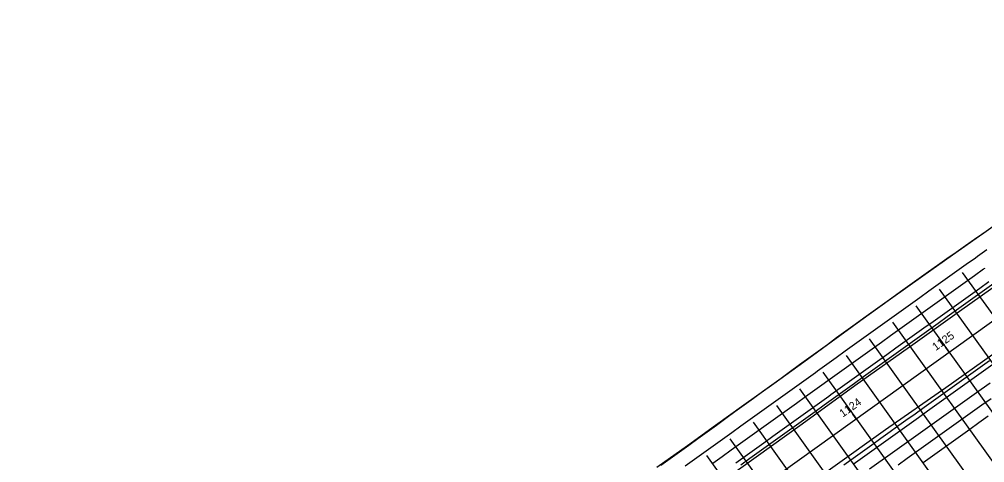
# Model space of a CAD drawing. Extents: x -354 to 8821, y -19535 to 19639.
# Drawn here: x 7398 to 8242, y 2193 to 2581 of the extents above; entities that cross this region are included whole.
import ezdxf

# ---------------------------------------------------------------- set-up
doc = ezdxf.new("R2010")
doc.units = 0
for name, color, linetype in [('PV_X_COP', 7, 'Continuous'), ('PV_X_EOP', 7, 'Continuous'), ('PV_X_Shoulder_Aggregate', 7, 'Continuous'), ('RW_X_CL_50', 7, 'Continuous'), ('SC_Scratch1', 7, 'Continuous')]:
    doc.layers.add(name, color=color, linetype=linetype)

msp = doc.modelspace()

# ---------------------------------------------------------------- linework, layer by layer
at = {"layer": 'PV_X_COP'}
for points in [[(8167.57, 2310.25), (8175.7, 2316.07), (8183.83, 2321.89), (8191.96, 2327.72), (8200.09, 2333.54), (8208.22, 2339.36), (8216.35, 2345.18), (8224.49, 2351), (8232.62, 2356.82), (8240.75, 2362.63), (8241.93, 2363.47)], [(8003.89, 2192.82), (8012.01, 2198.66), (8020.13, 2204.49), (8028.25, 2210.33), (8036.38, 2216.16), (8044.5, 2221.99), (8052.62, 2227.82), (8060.75, 2233.65), (8068.87, 2239.48), (8077, 2245.31), (8085.12, 2251.14), (8093.25, 2256.97), (8101.37, 2262.8), (8102.55, 2263.64), (8110.67, 2269.47), (8118.8, 2275.3), (8126.93, 2281.12), (8135.06, 2286.95), (8143.18, 2292.78), (8151.31, 2298.6), (8159.44, 2304.42), (8167.57, 2310.25)], [(8140.96, 2187.7), (8149.1, 2193.51), (8157.06, 2199.2), (8165.19, 2205.02), (8173.33, 2210.83), (8181.47, 2216.64), (8189.61, 2222.45), (8197.74, 2228.26), (8205.88, 2234.08), (8214.02, 2239.89), (8222.16, 2245.7), (8230.3, 2251.51), (8238.44, 2257.32), (8246.57, 2263.13)]]:
    msp.add_lwpolyline(points, dxfattribs=at)
at = {"layer": 'PV_X_EOP'}
for points in [[(8243.56, 2379.35), (8235.43, 2373.53), (8233.6, 2372.22), (8225.47, 2366.4), (8217.34, 2360.58), (8209.21, 2354.75), (8201.08, 2348.93), (8192.95, 2343.1), (8184.82, 2337.28), (8176.69, 2331.45), (8168.56, 2325.63), (8160.44, 2319.8), (8152.31, 2313.98), (8144.18, 2308.15), (8136.06, 2302.32), (8127.93, 2296.49), (8119.8, 2290.67), (8111.68, 2284.84), (8103.55, 2279.01), (8095.43, 2273.18), (8093.6, 2271.86), (8085.47, 2266.03), (8077.35, 2260.2), (8069.22, 2254.37), (8061.1, 2248.54), (8052.98, 2242.71), (8044.85, 2236.88), (8036.73, 2231.04), (8028.61, 2225.21), (8020.49, 2219.38), (8012.37, 2213.54), (8004.24, 2207.71), (7996.12, 2201.87), (7988, 2196.04), (7979.88, 2190.2)], [(8172.22, 2299.33), (8180.35, 2305.15), (8188.48, 2310.98), (8196.61, 2316.8), (8204.74, 2322.63), (8212.87, 2328.45), (8221, 2334.27), (8229.13, 2340.09), (8237.26, 2345.92), (8245.39, 2351.74)], [(8024.09, 2193.04), (8032.21, 2198.87), (8040.33, 2204.7), (8048.45, 2210.54), (8056.58, 2216.37), (8064.7, 2222.2), (8072.82, 2228.03), (8080.95, 2233.86), (8089.07, 2239.69), (8097.2, 2245.52), (8105.32, 2251.35), (8107.21, 2252.71), (8115.33, 2258.54), (8123.46, 2264.37), (8131.59, 2270.19), (8139.71, 2276.02), (8147.84, 2281.85), (8155.97, 2287.68), (8164.09, 2293.5), (8172.22, 2299.33)], [(8248.71, 2278.97), (8240.58, 2273.15), (8232.45, 2267.33), (8224.32, 2261.51), (8216.18, 2255.68), (8208.05, 2249.86), (8199.92, 2244.04), (8191.79, 2238.22), (8183.66, 2232.4), (8175.53, 2226.58), (8167.4, 2220.76), (8159.27, 2214.94), (8151.13, 2209.11), (8143, 2203.29), (8134.86, 2197.46), (8126.73, 2191.64)], [(8230.93, 2237.78), (8239.06, 2243.6), (8247.19, 2249.42)], [(8165.89, 2191.2), (8174.02, 2197.02), (8182.15, 2202.84), (8190.28, 2208.66), (8198.41, 2214.49), (8206.54, 2220.31), (8214.67, 2226.13), (8222.8, 2231.95), (8230.93, 2237.78)]]:
    msp.add_lwpolyline(points, dxfattribs=at)
at = {"layer": 'PV_X_Shoulder_Aggregate'}
for points in [[(8427.82, 2473.88), (8377.92, 2438.43), (8325.47, 2400.65), (8273.79, 2363.79), (8221.55, 2326.85), (8180.8, 2297.81), (8128.12, 2260.38), (8082.15, 2226.78), (8028.58, 2188.39), (7978.98, 2152.72), (7933.92, 2120.35), (7882.32, 2083.22), (7833.79, 2048.53), (7785.45, 2013.27), (7732.67, 1975.86), (7693.88, 1947.56), (7645.37, 1913.17), (7595.97, 1878.05), (7566.01, 1856.18)], [(8455.97, 2436.7), (8404.42, 2400.06), (8350.84, 2361.5), (8300.75, 2325.62), (8248.8, 2287.69), (8207.76, 2258.6), (8155.02, 2221.78), (8108.79, 2189.02), (8054.7, 2149.69), (8004.91, 2114.31), (7957.66, 2080.83), (7908.19, 2045.16), (7859.18, 2009.79), (7810.29, 1974.92), (7758.63, 1937.48), (7720.6, 1910.02), (7671.27, 1875.01), (7622.48, 1839.57), (7594.92, 1820.15)], [(8249.15, 2399.69), (8240.92, 2394.01), (8232.7, 2388.31), (8224.88, 2382.87), (8216.69, 2377.14), (8208.5, 2371.4), (8200.32, 2365.64), (8192.54, 2360.14), (8184.39, 2354.36), (8176.24, 2348.56), (8168.1, 2342.74), (8160.36, 2337.19), (8152.25, 2331.35), (8144.14, 2325.49), (8136.05, 2319.62), (8128.35, 2314.01), (8128.35, 2314.01), (8120.27, 2308.12), (8112.19, 2302.23), (8104.1, 2296.34), (8096.02, 2290.45), (8087.94, 2284.56), (8079.86, 2278.67), (8071.77, 2272.78), (8063.69, 2266.9), (8055.6, 2261.01), (8047.52, 2255.13), (8039.53, 2249.31), (8031.44, 2243.43), (8023.35, 2237.55), (8015.27, 2231.67), (8007.18, 2225.79), (7999.09, 2219.91), (7991, 2214.03), (7982.91, 2208.15), (7974.82, 2202.28), (7966.72, 2196.4), (7958.63, 2190.53)], [(7954.98, 2189.24), (7981.71, 2208.24), (8006.4, 2225.94), (8031.13, 2243.77), (8057.37, 2262.37), (8083.69, 2281.5), (8107.46, 2298.83), (8133.4, 2317.74), (8159.35, 2336.51), (8187.61, 2356.69), (8213.46, 2374.92), (8242.12, 2395.08)], [(8249.61, 2349.85), (8241.48, 2344.02), (8233.36, 2338.2), (8225.23, 2332.37), (8217.1, 2326.54), (8208.98, 2320.72), (8200.85, 2314.89), (8192.72, 2309.06), (8184.6, 2303.23), (8176.47, 2297.41), (8168.35, 2291.58), (8160.22, 2285.75), (8152.09, 2279.92), (8143.97, 2274.09), (8135.85, 2268.26), (8127.72, 2262.43), (8119.6, 2256.6), (8111.47, 2250.77), (8109.58, 2249.41), (8101.46, 2243.58), (8093.34, 2237.75), (8085.21, 2231.91), (8077.09, 2226.08), (8068.97, 2220.25), (8060.85, 2214.41), (8052.72, 2208.58), (8044.6, 2202.75), (8036.48, 2196.91), (8028.36, 2191.08)], [(8118.47, 2191.37), (8126.6, 2197.19), (8134.73, 2203.02), (8142.86, 2208.84), (8150.99, 2214.67), (8159.11, 2220.49), (8164.5, 2224.36), (8172.63, 2230.18), (8180.75, 2236.01), (8188.88, 2241.84), (8197.01, 2247.67), (8205.13, 2253.49), (8213.26, 2259.32), (8221.39, 2265.15), (8229.51, 2270.98), (8237.64, 2276.81), (8245.76, 2282.64)], [(8244.76, 2233.89), (8236.65, 2228.05), (8228.54, 2222.2), (8220.42, 2216.35), (8212.31, 2210.5), (8204.2, 2204.66), (8196.09, 2198.81), (8187.98, 2192.96)]]:
    msp.add_lwpolyline(points, dxfattribs=at)
at = {"layer": 'RW_X_CL_50'}
for p, q in [((7397.71, 1707.37), (8616.98, 2581.09)), ((8210.56, 2289.85), (8207.64, 2293.91)), ((8129.27, 2231.6), (8126.36, 2235.67))]:
    msp.add_line(p, q, dxfattribs=at)
at = {"layer": 'SC_Scratch1'}
for p, q in [((8222.07, 2359.62), (8455.07, 2034.48)), ((8201.75, 2345.05), (8434.75, 2019.92)), ((8181.43, 2330.49), (8414.43, 2005.36)), ((8161.11, 2315.93), (8394.1, 1990.79)), ((8140.79, 2301.37), (8373.78, 1976.23)), ((8120.47, 2286.81), (8353.46, 1961.67)), ((8100.15, 2272.24), (8333.14, 1947.11)), ((8079.83, 2257.68), (8312.82, 1932.55)), ((8059.51, 2243.12), (8292.5, 1917.98)), ((8039.19, 2228.56), (8272.18, 1903.42)), ((8018.86, 2214), (8251.86, 1888.86)), ((7998.54, 2199.43), (8231.54, 1874.3))]:
    msp.add_line(p, q, dxfattribs=at)

# ---------------------------------------------------------------- texts
at = {"layer": 'RW_X_CL_50'}
for s, p in [('1125', (8198.91, 2290.73)), ('1124', (8117.69, 2232.53))]:
    msp.add_text(s, height=7, rotation=35.62538, dxfattribs=at).set_placement(p)

doc.saveas('drawing.dxf')
